Omron CX-Programmer project NuevoProyecto (CX-Programmer 9.50)

# PLC NewPLC1: CP1L-E EM

## Program Lámparas (cyclic task 0)
Local symbols
Etapa_0 10.00 BOOL
Etapa_1 10.01 BOOL
Etapa_10 10.10 BOOL
Etapa_11 10.11 BOOL
Etapa_12 10.12 BOOL
Etapa_13 10.13 BOOL
Etapa_2 10.02 BOOL
Etapa_3 10.03 BOOL
Etapa_8 10.08 BOOL
Etapa_9 10.09 BOOL
H_1 100.00 BOOL
H_2 100.01 BOOL
H_3 100.02 BOOL
T_0 15.00 BOOL
m 0.00 BOOL

### Section Sección1_Programa_principal
; Programa principal (Etapas 0 ... 3)

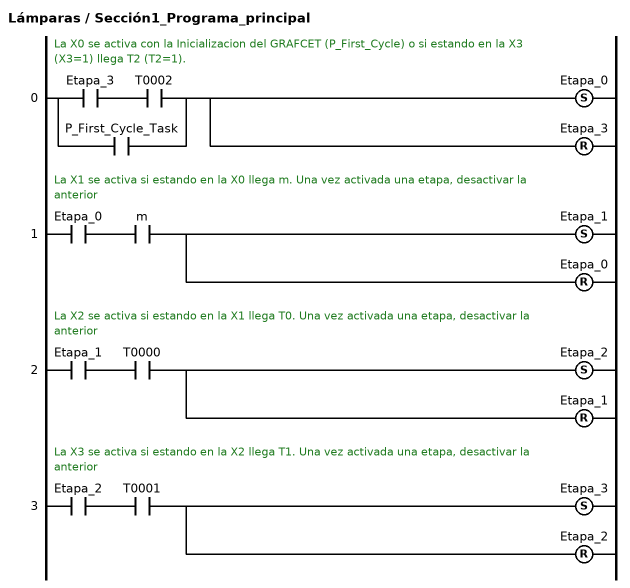
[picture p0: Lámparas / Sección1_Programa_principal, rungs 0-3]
; rung 0: La X0 se activa con la Inicializacion del GRAFCET (P_First_Cycle) o si estando en la X3 (X3=1) llega T2 (T2=1).
LD Etapa_3
AND T0002
OR P_First_Cycle_Task
SET Etapa_0
RSET Etapa_3  // Una vez activada una etapa, desactivar la anterior
; rung 1: La X1 se activa si estando en la X0 llega m. Una vez activada una etapa, desactivar la anterior
LD Etapa_0
AND m
SET Etapa_1
RSET Etapa_0
; rung 2: La X2 se activa si estando en la X1 llega T0. Una vez activada una etapa, desactivar la anterior
LD Etapa_1
AND T0000
SET Etapa_2
RSET Etapa_1
; rung 3: La X3 se activa si estando en la X2 llega T1. Una vez activada una etapa, desactivar la anterior
LD Etapa_2
AND T0001
SET Etapa_3
RSET Etapa_2

### Section Sección2_Temporizadores

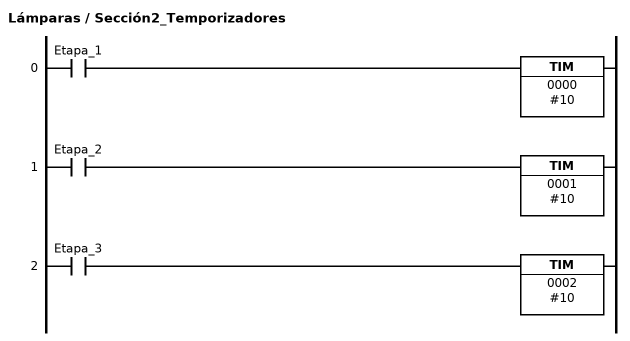
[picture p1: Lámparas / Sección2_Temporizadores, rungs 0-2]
; rung 0
LD Etapa_1
TIM 0000 #10
; rung 1
LD Etapa_2
TIM 0001 #10
; rung 2
LD Etapa_3
TIM 0002 #10

### Section Sección3_Salidas

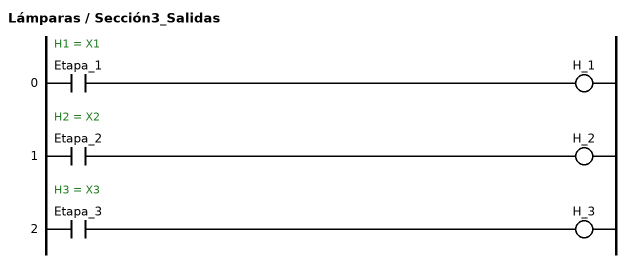
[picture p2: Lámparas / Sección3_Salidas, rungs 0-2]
; rung 0: H1 = X1
LD Etapa_1
OUT H_1
; rung 1: H2 = X2
LD Etapa_2
OUT H_2
; rung 2: H3 = X3
LD Etapa_3
OUT H_3

### Section Sección4_END
; rung 0: Fin de programa
END(001)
